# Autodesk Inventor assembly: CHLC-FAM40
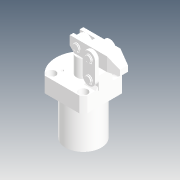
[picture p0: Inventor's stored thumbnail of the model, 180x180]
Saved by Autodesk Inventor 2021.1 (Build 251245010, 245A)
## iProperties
Company: Microsoft
Created: 2019-11
Part Number: CHLC-FAM40
Description: STEP AP214
Document SubType Name: Assembly
Designer: user
Title: CHLC-FAM40.STEP
Author: Windows
Revision Number: ÈÎºÎ
Sending System: SolidWorks 2015
Preprocessor: SwSTEP 2.0
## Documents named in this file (9)
- D:\Vault_2016\Projekty\Clamptek\Hydraulic\CHLC\CHLC-40\Inventor\CHLC-FAM40\CHLC-FAM40.iam
- D:\Vault_2016\Projekty\Clamptek\Hydraulic\CHLC\CHLC-40\Inventor\CHLC-FAM40\CHLC-FAM40-05_Ä¬ÈÏ[°´¼Ó¹¤].ipt
- D:\Vault_2016\Projekty\Clamptek\Hydraulic\CHLC\CHLC-40\Inventor\CHLC-FAM40\CHLC-40-01.ipt
- D:\Vault_2016\Projekty\Clamptek\Hydraulic\CHLC\CHLC-40\Inventor\CHLC-FAM40\CHLC-40-02.ipt
- D:\Vault_2016\Projekty\Clamptek\Hydraulic\CHLC\CHLC-40\Inventor\CHLC-FAM40\CHLC-40-03.ipt
- D:\Vault_2016\Projekty\Clamptek\Hydraulic\CHLC\CHLC-40\Inventor\CHLC-FAM40\CHLC-40-04.ipt
- D:\Vault_2016\Projekty\Clamptek\Hydraulic\CHLC\CHLC-40\Inventor\CHLC-FAM40\CHLC-40-06.ipt
- D:\Vault_2016\Projekty\Clamptek\Hydraulic\CHLC\CHLC-40\Inventor\CHLC-FAM40\CHLC-40-08.ipt
- D:\Vault_2016\Projekty\Clamptek\Hydraulic\CHLC\CHLC-40\Inventor\CHLC-FAM40\M6LS.ipt
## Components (18 placed, 18 different names)
1. CHLC-FAM40-05_Ä¬ÈÏ[°´¼Ó¹¤]_1
2. CHLC-40-01_2
3. CHLC-40-02_3
4. CHLC-40-03_4
5. CHLC-40-04_5
6. CHLC-40-06_6
7. CHLC-40-08_7
8. M6LS_8
9. CHLC-40-02_9
10. CHLC-40-06_10
11. CHLC-40-06_11
12. CHLC-40-06_12
13. CHLC-40-06_13
14. CHLC-40-06_14
15. M6LS_15
16. M6LS_16
17. M6LS_17
18. CHLC-40-03_18
